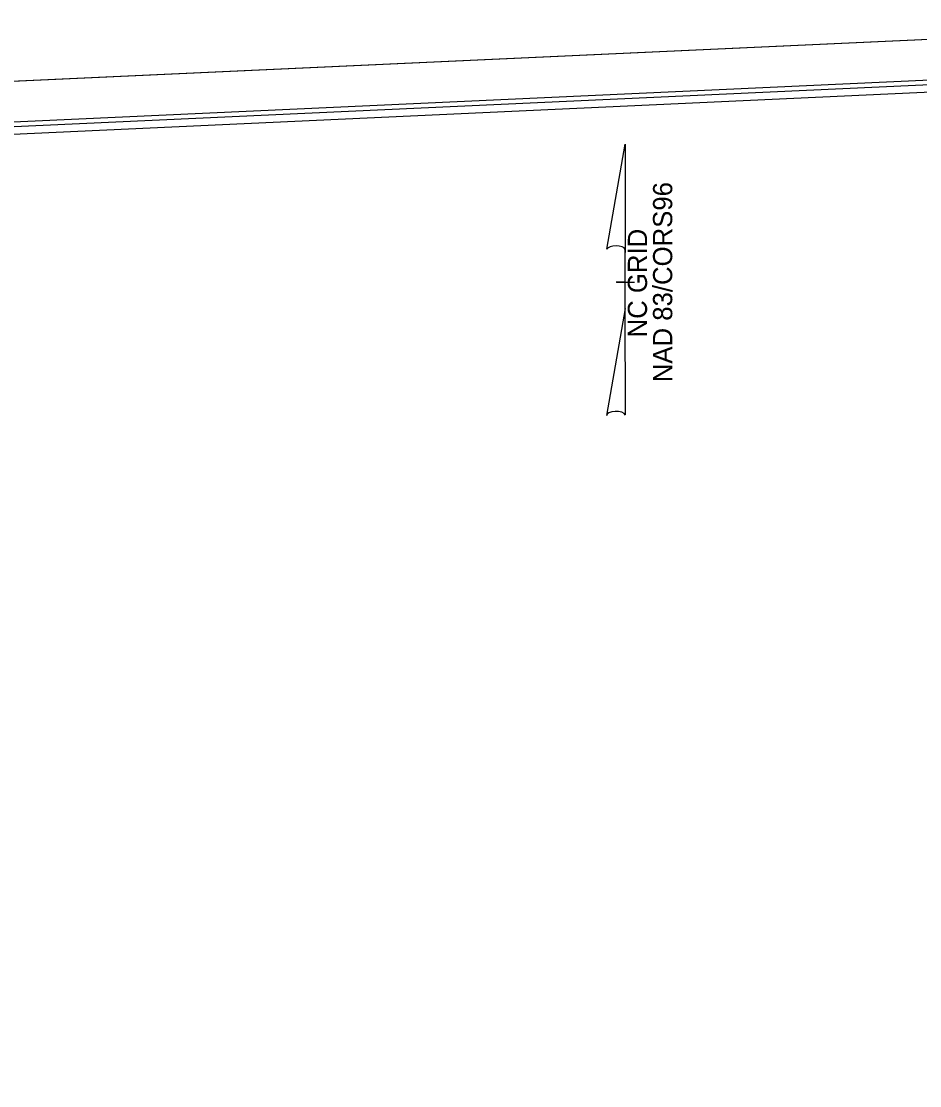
# Model space of a CAD drawing. Extents: x 1191070 to 1191932, y 892813 to 893283.
# Drawn here: x 1191500.7 to 1191699.2, y 893048.3 to 893283.5 of the extents above; entities that cross this region are included whole.
import ezdxf

# ---------------------------------------------------------------- set-up
doc = ezdxf.new("R2010")
doc.units = 0
for name, color, linetype in [('Prop North Arrow NAD83 for Plan Sheets CELL', 7, 'Continuous'), ('Sheet Border Standard 30in CELL', 7, 'Continuous'), ('Sheet Clip Boundary CELL', 7, 'Continuous'), ('Sheet Cutting Line CELL', 7, 'Continuous'), ('Sheet Plot Border Inside CELL', 7, 'Continuous'), ('Sheet Plot Border Outside CELL', 7, 'Continuous')]:
    doc.layers.add(name, color=color, linetype=linetype)

msp = doc.modelspace()

# ---------------------------------------------------------------- linework, layer by layer
at = {"layer": 'Prop North Arrow NAD83 for Plan Sheets CELL'}
for p, q in [((1191630.06, 893233.14), (1191634.16, 893256.31)), ((1191634.18, 893256.31), (1191634.18, 893232.41)), ((1191634.18, 893220.01), (1191634.18, 893233.11)), ((1191634.18, 893232.41), (1191634.18, 893233.09)), ((1191633.96, 893225.81), (1191632.18, 893225.81)), ((1191632.21, 893225.81), (1191636.21, 893225.81)), ((1191634.18, 893220.01), (1191630.01, 893196.39)), ((1191634.21, 893196.49), (1191634.18, 893220.01))]:
    msp.add_line(p, q, dxfattribs=at)
for centre, start_param, end_param in [((1191632.12, 893232.89), 0.216388, 2.908219), ((1191632.12, 893196.31), 0.201328, 3.141593)]:
    msp.add_ellipse(centre, major_axis=(2.11, -0.02), ratio=0.461098, start_param=start_param, end_param=end_param, dxfattribs=at)
at = {"layer": 'Sheet Border Standard 30in CELL'}
msp.add_lwpolyline([(1191783.48, 893273.17), (1191184.11, 893245.75), (1191203.31, 892826.19), (1191802.68, 892853.61)], close=True, dxfattribs=at)
at = {"layer": 'Sheet Clip Boundary CELL'}
msp.add_lwpolyline([(1191201.31, 892936.07), (1191187.08, 893244.15), (1191703.39, 893267.99), (1191706.1, 893208.66), (1191782.81, 893212.17), (1191794.3, 892963.46), (1191451.08, 892947.61)], close=True, dxfattribs=at)
at = {"layer": 'Sheet Cutting Line CELL'}
msp.add_line((1191789.82, 893283.47), (1191116.92, 893252.68), dxfattribs=at)
at = {"layer": 'Sheet Plot Border Inside CELL'}
msp.add_lwpolyline([(1191788.43, 893274.42), (1191122.53, 893243.95), (1191141.82, 892822.35), (1191807.72, 892852.82)], close=True, dxfattribs=at)
at = {"layer": 'Sheet Plot Border Outside CELL'}
msp.add_lwpolyline([(1191789.82, 893283.47), (1191116.92, 893252.68), (1191137.03, 892813.14), (1191809.93, 892843.93)], close=True, dxfattribs=at)

# ---------------------------------------------------------------- texts
at = {"layer": 'Prop North Arrow NAD83 for Plan Sheets CELL'}
for s, p in [('NAD 83/CORS96', (1191644.55, 893203.73)), ('NC GRID', (1191638.98, 893213.63))]:
    msp.add_text(s, height=4.25, rotation=90, dxfattribs=at).set_placement(p)

doc.saveas('drawing.dxf')
